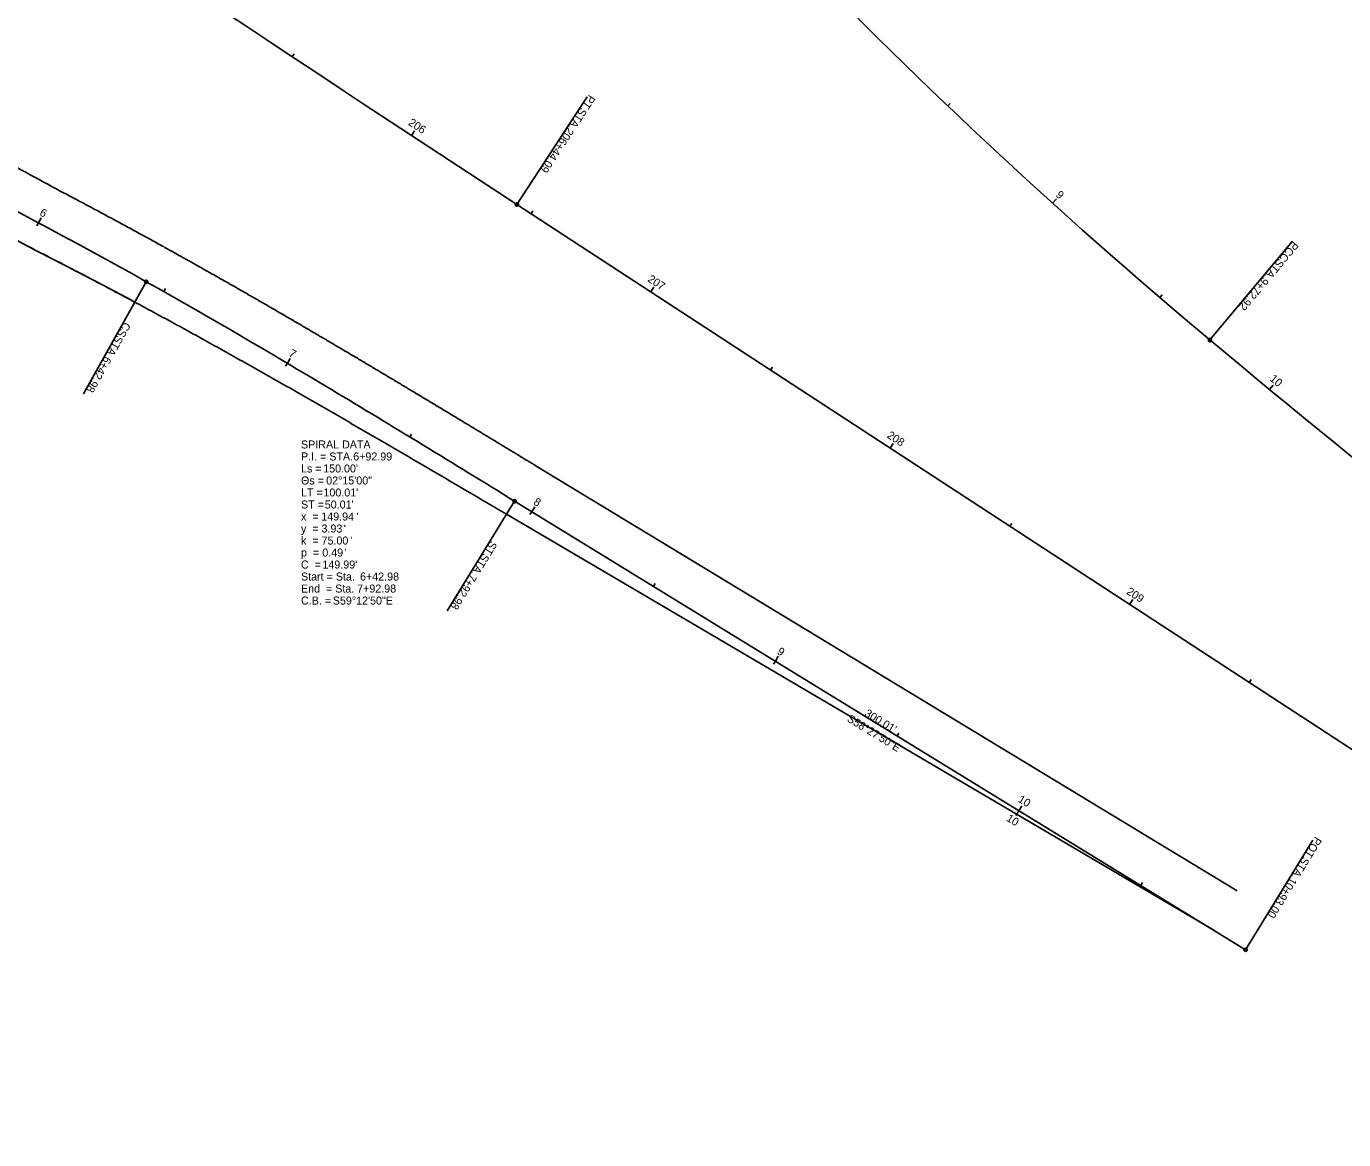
# Model space of a CAD drawing. Extents: x 1323137 to 1326838, y 458936 to 461644.
# Drawn here: x 1325549.7 to 1326010.6, y 459319.9 to 459709.4 of the extents above; entities that cross this region are included whole.
import ezdxf

# ---------------------------------------------------------------- set-up
doc = ezdxf.new("R2010")
doc.units = 0
for name, color, linetype in [('_CIVIL_CONSTRUCTION', 7, 'Continuous'), ('CM_Corridor_Range_Final', 7, 'Continuous'), ('Default', 7, 'Continuous'), ('DT_P_Graded_Shoulder', 7, 'Continuous'), ('DT_P_Tie', 7, 'Continuous'), ('MD_P_ACB_B', 7, 'Continuous'), ('MD_P_ACB_T', 7, 'Continuous'), ('MD_P_ACIC_B', 7, 'Continuous'), ('MD_P_ACSC_B', 7, 'Continuous'), ('MD_P_ACSC_T', 7, 'Continuous'), ('MD_P_AGB_B', 7, 'Continuous'), ('MD_P_AGB_T', 7, 'Continuous'), ('MD_P_Surface_Asphalt_Concrete_Intermediate_Course', 7, 'Continuous'), ('PV_P_Shoulder', 7, 'Continuous'), ('SG_P_Conduit', 7, 'Continuous'), ('SG_P_Mast_Arm', 7, 'Continuous'), ('SN_P_Signs', 7, 'Continuous'), ('SN_X_Public', 7, 'Continuous')]:
    doc.layers.add(name, color=color, linetype=linetype)

msp = doc.modelspace()

# ---------------------------------------------------------------- linework, layer by layer
at = {"layer": '_CIVIL_CONSTRUCTION'}
msp.add_line((1325721.36, 459647), (1325745.96, 459684.68), dxfattribs=at)
msp.add_circle((1325721.36, 459647), 0.6, dxfattribs=at)
at = {"layer": 'CM_Corridor_Range_Final'}
for p, q in [((1325642.76, 459698.72), (1325643.43, 459699.72)), ((1325684.48, 459671.16), (1325685.58, 459672.83)), ((1325726.31, 459643.77), (1325726.97, 459644.77)), ((1325768.19, 459616.44), (1325769.28, 459618.12)), ((1325810.06, 459589.12), (1325810.71, 459590.12)), ((1325851.93, 459561.79), (1325853.02, 459563.47)), ((1325893.8, 459534.47), (1325894.46, 459535.47)), ((1325935.68, 459507.14), (1325936.77, 459508.82)), ((1325977.55, 459479.82), (1325978.21, 459480.82))]:
    msp.add_line(p, q, dxfattribs=at)
at = {"layer": 'Default'}
for p, q in [((1325721.36, 459647), (1326810.06, 458936.55)), ((1325720.55, 459543.25), (1325976.25, 459386.34))]:
    msp.add_line(p, q, dxfattribs=at)
msp.add_lwpolyline([(1325586.72, 459613.4), (1325584.96, 459614.34), (1325576.17, 459619), (1325567.35, 459623.63), (1325558.51, 459628.2), (1325549.7, 459632.7)], dxfattribs=at)
for centre, radius, start, end in [((1332431.06, 469929.07), 12277.67, 232.043309, 236.873031), ((1327189.47, 461064.32), 1909.86, 217.49136, 230.07643), ((1324657.44, 457954.27), 1909.86, 60.71386, 66.05442), ((1328414.31, 462527.99), 3818.4, 230.07643, 236.87482)]:
    msp.add_arc(centre, radius, start, end, dxfattribs=at)
msp.add_open_spline([(1325591.69, 459620.02), (1325602.6, 459613.91), (1325624.29, 459601.49), (1325656.52, 459582.31), (1325688.6, 459562.89), (1325709.89, 459549.79), (1325720.55, 459543.25)], degree=3, dxfattribs=at)
at = {"layer": 'DT_P_Tie'}
for p, q in [((1325560.26, 459652.46), (1325560.34, 459652.41)), ((1325560.26, 459652.46), (1325560.34, 459652.41)), ((1325727.79, 459555.76), (1325973.28, 459406.92)), ((1325727.79, 459555.76), (1325973.28, 459406.92)), ((1325717.73, 459538.67), (1325965.17, 459393.13)), ((1325717.73, 459538.67), (1325965.17, 459393.13))]:
    msp.add_line(p, q, dxfattribs=at)
msp.add_arc((1324657.44, 457954.27), 1900.86, 62.00341, 65.30341, dxfattribs=at)
msp.add_arc((1324657.44, 457954.27), 1900.86, 62.00341, 65.30341, dxfattribs=at)
for points, degree in [([(1325461.62, 459702.94), (1325463.28, 459702.14), (1325466.62, 459700.55), (1325471.61, 459698.15), (1325476.6, 459695.73), (1325481.58, 459693.3), (1325486.56, 459690.85), (1325491.52, 459688.39), (1325496.48, 459685.91), (1325501.43, 459683.42), (1325506.37, 459680.92), (1325511.31, 459678.4), (1325516.24, 459675.87), (1325521.16, 459673.33), (1325526.08, 459670.77), (1325530.98, 459668.19), (1325535.88, 459665.61), (1325540.77, 459663), (1325545.66, 459660.39), (1325550.53, 459657.76), (1325555.4, 459655.12), (1325558.64, 459653.34), (1325560.26, 459652.46)], 3), ([(1325461.62, 459702.94), (1325463.28, 459702.14), (1325466.62, 459700.55), (1325471.61, 459698.15), (1325476.6, 459695.73), (1325481.58, 459693.3), (1325486.56, 459690.85), (1325491.52, 459688.39), (1325496.48, 459685.91), (1325501.43, 459683.42), (1325506.37, 459680.92), (1325511.31, 459678.4), (1325516.24, 459675.87), (1325521.16, 459673.33), (1325526.08, 459670.77), (1325530.98, 459668.19), (1325535.88, 459665.61), (1325540.77, 459663), (1325545.66, 459660.39), (1325550.53, 459657.76), (1325555.4, 459655.12), (1325558.64, 459653.34), (1325560.26, 459652.46)], 3), ([(1325560.34, 459652.41), (1325560.68, 459652.23), (1325561.76, 459651.66), (1325563.8, 459650.59), (1325565.61, 459649.64), (1325567.55, 459648.61), (1325569.46, 459647.6), (1325571.37, 459646.58), (1325573.28, 459645.56), (1325575.19, 459644.54), (1325577.1, 459643.51), (1325579, 459642.49), (1325580.91, 459641.46), (1325582.81, 459640.43), (1325584.71, 459639.4), (1325586.62, 459638.36), (1325588.52, 459637.32), (1325590.41, 459636.29), (1325592.34, 459635.23), (1325594.13, 459634.25), (1325596.4, 459632.99), (1325597.64, 459632.31), (1325598, 459632.11)], 3), ([(1325560.34, 459652.41), (1325560.68, 459652.23), (1325561.76, 459651.66), (1325563.8, 459650.59), (1325565.61, 459649.64), (1325567.55, 459648.61), (1325569.46, 459647.6), (1325571.37, 459646.58), (1325573.28, 459645.56), (1325575.19, 459644.54), (1325577.1, 459643.51), (1325579, 459642.49), (1325580.91, 459641.46), (1325582.81, 459640.43), (1325584.71, 459639.4), (1325586.62, 459638.36), (1325588.52, 459637.32), (1325590.41, 459636.29), (1325592.34, 459635.23), (1325594.13, 459634.25), (1325596.4, 459632.99), (1325597.64, 459632.31), (1325598, 459632.11)], 3), ([(1325549.74, 459632.68), (1325550.38, 459632.36), (1325551.65, 459631.71), (1325553.56, 459630.74), (1325555.46, 459629.76), (1325557.37, 459628.79), (1325559.27, 459627.81), (1325561.17, 459626.83), (1325563.07, 459625.85), (1325564.97, 459624.86), (1325566.87, 459623.87), (1325568.77, 459622.89), (1325570.67, 459621.89), (1325572.56, 459620.9), (1325574.45, 459619.91), (1325576.35, 459618.91), (1325578.24, 459617.91), (1325580.13, 459616.91), (1325582.02, 459615.9), (1325583.91, 459614.9), (1325585.8, 459613.89), (1325587.06, 459613.21), (1325587.69, 459612.88)], 3), ([(1325549.74, 459632.68), (1325550.38, 459632.36), (1325551.65, 459631.71), (1325553.56, 459630.74), (1325555.46, 459629.76), (1325557.37, 459628.79), (1325559.27, 459627.81), (1325561.17, 459626.83), (1325563.07, 459625.85), (1325564.97, 459624.86), (1325566.87, 459623.87), (1325568.77, 459622.89), (1325570.67, 459621.89), (1325572.56, 459620.9), (1325574.45, 459619.91), (1325576.35, 459618.91), (1325578.24, 459617.91), (1325580.13, 459616.91), (1325582.02, 459615.9), (1325583.91, 459614.9), (1325585.8, 459613.89), (1325587.06, 459613.21), (1325587.69, 459612.88)], 3), ([(1325598.02, 459632.1), (1325599.26, 459631.41), (1325603.59, 459629.01), (1325611.5, 459624.58), (1325617.73, 459621.05), (1325624.39, 459617.26), (1325630.91, 459613.51), (1325637.45, 459609.73), (1325643.97, 459605.93), (1325650.48, 459602.12), (1325656.97, 459598.3), (1325663.46, 459594.47), (1325669.93, 459590.62), (1325676.39, 459586.77), (1325682.84, 459582.91), (1325689.28, 459579.04), (1325695.72, 459575.16), (1325702.12, 459571.3), (1325708.63, 459567.36), (1325714.71, 459563.68), (1325722.37, 459559.04), (1325726.57, 459556.49), (1325727.79, 459555.76)], 2), ([(1325598.02, 459632.1), (1325599.26, 459631.41), (1325603.59, 459629.01), (1325611.5, 459624.58), (1325617.73, 459621.05), (1325624.39, 459617.26), (1325630.91, 459613.51), (1325637.45, 459609.73), (1325643.97, 459605.93), (1325650.48, 459602.12), (1325656.97, 459598.3), (1325663.46, 459594.47), (1325669.93, 459590.62), (1325676.39, 459586.77), (1325682.84, 459582.91), (1325689.28, 459579.04), (1325695.72, 459575.16), (1325702.12, 459571.3), (1325708.63, 459567.36), (1325714.71, 459563.68), (1325722.37, 459559.04), (1325726.57, 459556.49), (1325727.79, 459555.76)], 2), ([(1325587.69, 459612.88), (1325589.88, 459611.7), (1325594.26, 459609.34), (1325600.83, 459605.77), (1325607.38, 459602.17), (1325613.93, 459598.56), (1325620.46, 459594.92), (1325626.98, 459591.26), (1325633.5, 459587.58), (1325640.01, 459583.89), (1325646.51, 459580.18), (1325653, 459576.45), (1325659.49, 459572.71), (1325665.98, 459568.96), (1325672.45, 459565.2), (1325678.93, 459561.43), (1325685.4, 459557.65), (1325691.87, 459553.86), (1325698.34, 459550.07), (1325704.8, 459546.27), (1325711.27, 459542.47), (1325715.58, 459539.93), (1325717.73, 459538.67)], 3), ([(1325587.69, 459612.88), (1325589.88, 459611.7), (1325594.26, 459609.34), (1325600.83, 459605.77), (1325607.38, 459602.17), (1325613.93, 459598.56), (1325620.46, 459594.92), (1325626.98, 459591.26), (1325633.5, 459587.58), (1325640.01, 459583.89), (1325646.51, 459580.18), (1325653, 459576.45), (1325659.49, 459572.71), (1325665.98, 459568.96), (1325672.45, 459565.2), (1325678.93, 459561.43), (1325685.4, 459557.65), (1325691.87, 459553.86), (1325698.34, 459550.07), (1325704.8, 459546.27), (1325711.27, 459542.47), (1325715.58, 459539.93), (1325717.73, 459538.67)], 3)]:
    msp.add_open_spline(points, degree=degree, dxfattribs=at)
at = {"layer": 'MD_P_ACB_B'}
for p, q in [((1325963.79, 459599.65), (1325992.67, 459634.16)), ((1325591.69, 459620.02), (1325569.68, 459580.77)), ((1325720.55, 459543.25), (1325697.01, 459504.9)), ((1325976.25, 459386.34), (1325999.79, 459424.69))]:
    msp.add_line(p, q, dxfattribs=at)
for centre in [(1325591.69, 459620.02), (1325963.79, 459599.65), (1325720.55, 459543.25), (1325976.25, 459386.34)]:
    msp.add_circle(centre, 0.6, dxfattribs=at)
at = {"layer": 'MD_P_ACSC_B'}
for p, q in [((1325591.69, 459620.02), (1325569.68, 459580.77)), ((1325720.55, 459543.25), (1325697.01, 459504.9)), ((1325976.25, 459386.34), (1325999.79, 459424.69))]:
    msp.add_line(p, q, dxfattribs=at)
for centre in [(1325591.69, 459620.02), (1325720.55, 459543.25), (1325976.25, 459386.34)]:
    msp.add_circle(centre, 0.6, dxfattribs=at)
at = {"layer": 'MD_P_Surface_Asphalt_Concrete_Intermediate_Course'}
msp.add_line((1325721.36, 459647), (1325745.96, 459684.68), dxfattribs=at)
msp.add_circle((1325721.36, 459647), 0.6, dxfattribs=at)
at = {"layer": 'PV_P_Shoulder'}
for p, q in [((1325553.97, 459640.63), (1325553.41, 459639.57)), ((1325641.05, 459591.49), (1325640.44, 459590.46)), ((1325726.53, 459539.58), (1325725.9, 459538.56)), ((1325811.76, 459487.28), (1325811.13, 459486.26)), ((1325896.99, 459434.98), (1325895.94, 459433.27))]:
    msp.add_line(p, q, dxfattribs=at)
at = {"layer": 'SG_P_Conduit'}
msp.add_line((1325720.55, 459543.25), (1325976.25, 459386.34), dxfattribs=at)
for centre, radius, start, end in [((1327189.47, 461064.32), 1909.86, 217.49136, 230.07643), ((1324657.44, 457954.27), 1909.86, 60.71386, 66.05442), ((1328414.31, 462527.99), 3818.4, 230.07643, 236.87482)]:
    msp.add_arc(centre, radius, start, end, dxfattribs=at)
msp.add_open_spline([(1325591.69, 459620.02), (1325602.6, 459613.91), (1325624.29, 459601.49), (1325656.52, 459582.31), (1325688.6, 459562.89), (1325709.89, 459549.79), (1325720.55, 459543.25)], degree=3, dxfattribs=at)
at = {"layer": 'SG_P_Mast_Arm'}
for p, q in [((1325872.13, 459681.52), (1325872.95, 459682.38)), ((1325908.77, 459647.5), (1325910.12, 459648.99)), ((1325553.97, 459640.63), (1325554.91, 459642.39)), ((1325597.81, 459616.58), (1325598.4, 459617.62)), ((1325946.3, 459614.47), (1325947.08, 459615.38)), ((1325641.05, 459591.49), (1325642.07, 459593.21)), ((1325984.62, 459582.35), (1325985.89, 459583.89)), ((1325683.89, 459565.7), (1325684.51, 459566.72)), ((1325726.53, 459539.58), (1325727.57, 459541.29)), ((1325769.14, 459513.43), (1325769.77, 459514.45)), ((1325811.76, 459487.28), (1325812.8, 459488.98)), ((1325854.37, 459461.13), (1325855, 459462.15)), ((1325896.99, 459434.98), (1325898.03, 459436.68)), ((1325939.6, 459408.82), (1325940.23, 459409.85))]:
    msp.add_line(p, q, dxfattribs=at)
at = {"layer": 'SN_P_Signs'}
for p, q in [((1325721.36, 459647), (1326810.06, 458936.55)), ((1325720.55, 459543.25), (1325976.25, 459386.34))]:
    msp.add_line(p, q, dxfattribs=at)
for centre, radius, start, end in [((1332431.06, 469929.07), 12277.67, 232.043309, 236.873031), ((1327189.47, 461064.32), 1909.86, 217.49136, 230.07643), ((1324657.44, 457954.27), 1909.86, 60.71386, 66.05442), ((1328414.31, 462527.99), 3818.4, 230.07643, 236.87482)]:
    msp.add_arc(centre, radius, start, end, dxfattribs=at)
msp.add_open_spline([(1325591.69, 459620.02), (1325602.6, 459613.91), (1325624.29, 459601.49), (1325656.52, 459582.31), (1325688.6, 459562.89), (1325709.89, 459549.79), (1325720.55, 459543.25)], degree=3, dxfattribs=at)
at = {"layer": 'SN_X_Public'}
for p, q in [((1325684.48, 459671.16), (1325685.14, 459672.16)), ((1325768.19, 459616.44), (1325768.84, 459617.45)), ((1325851.93, 459561.79), (1325852.59, 459562.8)), ((1325935.68, 459507.14), (1325936.33, 459508.15))]:
    msp.add_line(p, q, dxfattribs=at)

# ---------------------------------------------------------------- texts
at = {"layer": '_CIVIL_CONSTRUCTION'}
for s, p in [('PT', (1325746.63, 459685.64)), (' STA. ', (1325744.25, 459682)), ('206+44.09', (1325739.15, 459674.19))]:
    msp.add_text(s, height=2.8, rotation=236.873, dxfattribs=at).set_placement(p)
at = {"layer": 'CM_Corridor_Range_Final'}
for s, rotation, p in [('206', 326.6673, (1325683.14, 459675.04)), ('207', 326.873, (1325766.84, 459620.31)), ('208', 326.873, (1325850.58, 459565.66)), ('209', 326.873, (1325934.34, 459511))]:
    msp.add_text(s, height=2.8, rotation=rotation, dxfattribs=at).set_placement(p)
at = {"layer": 'DT_P_Graded_Shoulder'}
msp.add_text('S58°27\'50"E', height=2.8, rotation=328.4639, dxfattribs=at).set_placement((1325836.57, 459466.42))
at = {"layer": 'MD_P_ACB_B'}
for s, rotation, p in [('PCC', 230.0764, (1325992.92, 459634.4)), (' STA. ', 230.0764, (1325988.5, 459629.11)), ('9+72.92', 230.0764, (1325982.44, 459621.86)), ('CS', 240.7139, (1325583.95, 459606.14)), (' STA. ', 240.7139, (1325581.85, 459602.39)), ('6+42.98', 240.7139, (1325577.23, 459594.14)), ('ST', 238.4639, (1325712.22, 459529.6)), (' STA. ', 238.4639, (1325710.07, 459526.09)), ('7+92.98', 238.4639, (1325705.12, 459518.04)), ('POT', 238.4639, (1326000.7, 459426.1)), (' STA. ', 238.4639, (1325996.94, 459419.96)), ('10+93.00', 238.4639, (1325991.99, 459411.91))]:
    msp.add_text(s, height=2.8, rotation=rotation, dxfattribs=at).set_placement(p)
at = {"layer": 'MD_P_ACB_T'}
msp.add_text("300.01'", height=2.8, rotation=328.4639, dxfattribs=at).set_placement((1325842.73, 459468.32))
at = {"layer": 'MD_P_ACIC_B'}
msp.add_text('S58°27\'50"E', height=2.8, rotation=328.4639, dxfattribs=at).set_placement((1325836.57, 459466.42))
at = {"layer": 'MD_P_ACSC_B'}
for s, rotation, p in [('CS', 240.7139, (1325583.95, 459606.14)), (' STA. ', 240.7139, (1325581.85, 459602.39)), ('6+42.98', 240.7139, (1325577.23, 459594.14)), ('ST', 238.4639, (1325712.22, 459529.6)), (' STA. ', 238.4639, (1325710.07, 459526.09)), ('7+92.98', 238.4639, (1325705.12, 459518.04)), ('POT', 238.4639, (1326000.7, 459426.1)), (' STA. ', 238.4639, (1325996.94, 459419.96)), ('10+93.00', 238.4639, (1325991.99, 459411.91))]:
    msp.add_text(s, height=2.8, rotation=rotation, dxfattribs=at).set_placement(p)
at = {"layer": 'MD_P_ACSC_T'}
msp.add_text("300.01'", height=2.8, rotation=328.4639, dxfattribs=at).set_placement((1325842.73, 459468.32))
at = {"layer": 'MD_P_AGB_B'}
for s, p in [('SPIRAL DATA', (1325645.83, 459561.69)), ('P.I. = STA. ', (1325645.83, 459557.49)), ('6+92.99', (1325664.09, 459557.49)), ('Ls = ', (1325645.83, 459553.29)), ("150.00'", (1325653.59, 459553.29)), ('Θs = ', (1325645.83, 459549.09)), ('02°15\'00"', (1325654.63, 459549.09)), ('LT = ', (1325645.83, 459544.89)), ("100.01'", (1325653.68, 459544.89)), ('ST = ', (1325645.83, 459540.69)), ("50.01'", (1325654.14, 459540.69)), ('x  = ', (1325645.83, 459536.49)), ('3.93', (1325652.99, 459532.29)), ('149.94', (1325652.93, 459536.49)), ("'", (1325665.21, 459536.49)), ('y  = ', (1325645.83, 459532.29)), ('k  = ', (1325645.83, 459528.09)), ('75.00', (1325653.02, 459528.09)), ("'", (1325660.81, 459532.29)), ("'", (1325663.07, 459528.09)), ('p  = ', (1325645.83, 459523.89)), ('0.49', (1325653.28, 459523.89)), ("'", (1325661.1, 459523.89)), ('C  = ', (1325645.83, 459519.69)), ("149.99'", (1325653.32, 459519.69)), ('Start = Sta. ', (1325645.83, 459515.49)), ('6+42.98', (1325666.48, 459515.49)), ('End  = Sta. ', (1325645.83, 459511.29)), ('7+92.98', (1325665.46, 459511.29)), ('C.B. = ', (1325645.83, 459507.09)), ('S59°12\'50"E', (1325656.95, 459507.09))]:
    msp.add_text(s, height=2.8, dxfattribs=at).set_placement(p)
at = {"layer": 'MD_P_AGB_T'}
for s, p in [('SPIRAL DATA', (1325645.83, 459561.69)), ('P.I. = STA. ', (1325645.83, 459557.49)), ('6+92.99', (1325664.09, 459557.49)), ('Ls = ', (1325645.83, 459553.29)), ("150.00'", (1325653.59, 459553.29)), ('Θs = ', (1325645.83, 459549.09)), ('02°15\'00"', (1325654.63, 459549.09)), ('LT = ', (1325645.83, 459544.89)), ("100.01'", (1325653.68, 459544.89)), ('ST = ', (1325645.83, 459540.69)), ("50.01'", (1325654.14, 459540.69)), ('x  = ', (1325645.83, 459536.49)), ('3.93', (1325652.99, 459532.29)), ('149.94', (1325652.93, 459536.49)), ("'", (1325665.21, 459536.49)), ('y  = ', (1325645.83, 459532.29)), ('k  = ', (1325645.83, 459528.09)), ('75.00', (1325653.02, 459528.09)), ("'", (1325660.81, 459532.29)), ("'", (1325663.07, 459528.09)), ('p  = ', (1325645.83, 459523.89)), ('0.49', (1325653.28, 459523.89)), ("'", (1325661.1, 459523.89)), ('C  = ', (1325645.83, 459519.69)), ("149.99'", (1325653.32, 459519.69)), ('Start = Sta. ', (1325645.83, 459515.49)), ('6+42.98', (1325666.48, 459515.49)), ('End  = Sta. ', (1325645.83, 459511.29)), ('7+92.98', (1325665.46, 459511.29)), ('C.B. = ', (1325645.83, 459507.09)), ('S59°12\'50"E', (1325656.95, 459507.09))]:
    msp.add_text(s, height=2.8, dxfattribs=at).set_placement(p)
at = {"layer": 'MD_P_Surface_Asphalt_Concrete_Intermediate_Course'}
for s, p in [('PT', (1325746.63, 459685.64)), (' STA. ', (1325744.25, 459682)), ('206+44.09', (1325739.15, 459674.19))]:
    msp.add_text(s, height=2.8, rotation=236.873, dxfattribs=at).set_placement(p)
at = {"layer": 'PV_P_Shoulder'}
msp.add_text('10', height=2.8, rotation=328.4639, dxfattribs=at).set_placement((1325892.32, 459431.63))
at = {"layer": 'SG_P_Mast_Arm'}
for s, rotation, p in [('9', 317.8888, (1325909.65, 459650.09)), ('6', 332.0034, (1325554.15, 459643.36)), ('7', 329.3285, (1325641.31, 459594.24)), ('10', 320.4827, (1325984.49, 459585.69)), ('8', 328.4639, (1325726.9, 459542.29)), ('9', 328.4639, (1325812.14, 459489.98)), ('10', 328.4639, (1325896.4, 459438.27))]:
    msp.add_text(s, height=2.8, rotation=rotation, dxfattribs=at).set_placement(p)

doc.saveas('drawing.dxf')
